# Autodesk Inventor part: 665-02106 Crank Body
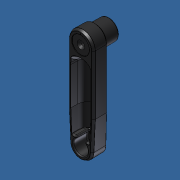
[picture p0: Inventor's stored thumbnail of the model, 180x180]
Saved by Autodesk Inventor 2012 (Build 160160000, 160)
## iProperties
Created: 2013-10
Part Number: 665-02106 Crank Body
Material: Default
Document SubType Name: Modeling
Designer: Admin
Density: 1 g/cm^3
Author: Admin
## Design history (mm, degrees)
node "665-02106 Crank Body1"
node "Base1"
body "Solid1"
